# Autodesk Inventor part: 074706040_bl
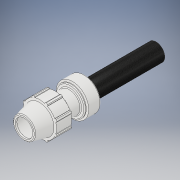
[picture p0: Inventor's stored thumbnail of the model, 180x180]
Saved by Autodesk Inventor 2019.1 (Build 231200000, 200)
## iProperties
Created: 2022-07
Part Number: 074706040_bl
Material: PVC-Piping
Description: Plasson Adjustable Elbow 40 x 40 mm
Document SubType Name: Modeling
Designer: comp2
Density: 1.4 g/cm^3
Appearance: Smooth - White
Author: comp2
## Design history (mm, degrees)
derived "07470.ipt"
feature "Solid1::07470.ipt" dims "ScaleForDerivedMember" = 10
feature "Solid2::07470.ipt" dims "ScaleForDerivedMember" = 10
feature "Solid3::07470.ipt" dims "ScaleForDerivedMember" = 10
feature "Solid4::07470.ipt" dims "ScaleForDerivedMember" = 10
tag "TaggingFeature1"
body "Solid1"
body "Solid2"
body "Solid3"
body "Solid4"
other parameters: "d0" = 301 [user parameter], "d6" = 82 [user parameter], "d7" = 32.8 [user parameter], "d9" = 45 deg [user parameter], "d11" = 153 [user parameter], "d12" = 44 [user parameter], "d13" = 191.25 [user parameter], "d14" = 76.5 [user parameter], "d15" = 1 [user parameter], "d16" = 27.54 [user parameter], "d17" = 58 [user parameter], "d19" = 66 [user parameter], "d20" = 8 deg [user parameter], "d21" = 30.45 [user parameter], "d22" = 4 [user parameter], "d24" = 8 [user parameter], "d25" = 1.505 [user parameter], "d26" = 1.505 [user parameter], "d27" = 85 deg [user parameter], "d28" = 87 [user parameter], "d30" = 34.8 [user parameter], "d31" = 2 [user parameter], "d32" = 34 [user parameter], "d33" = 3.48 [user parameter], "d38" = 76.26 [user parameter], "d39" = 35 deg [user parameter], "d40" = 17.5 deg [user parameter], "d42" = 0 [user parameter], "d43" = 1.64 [user parameter], "d47" = 360 deg [user parameter], "d49" = 2 [user parameter], "d50" = 7.83 [user parameter], "l1" = 153 [user parameter], "l_" = 87 [user parameter], "H_" = 301 [user parameter], "E_" = 82 [user parameter], "d23" = 8 [user parameter]
